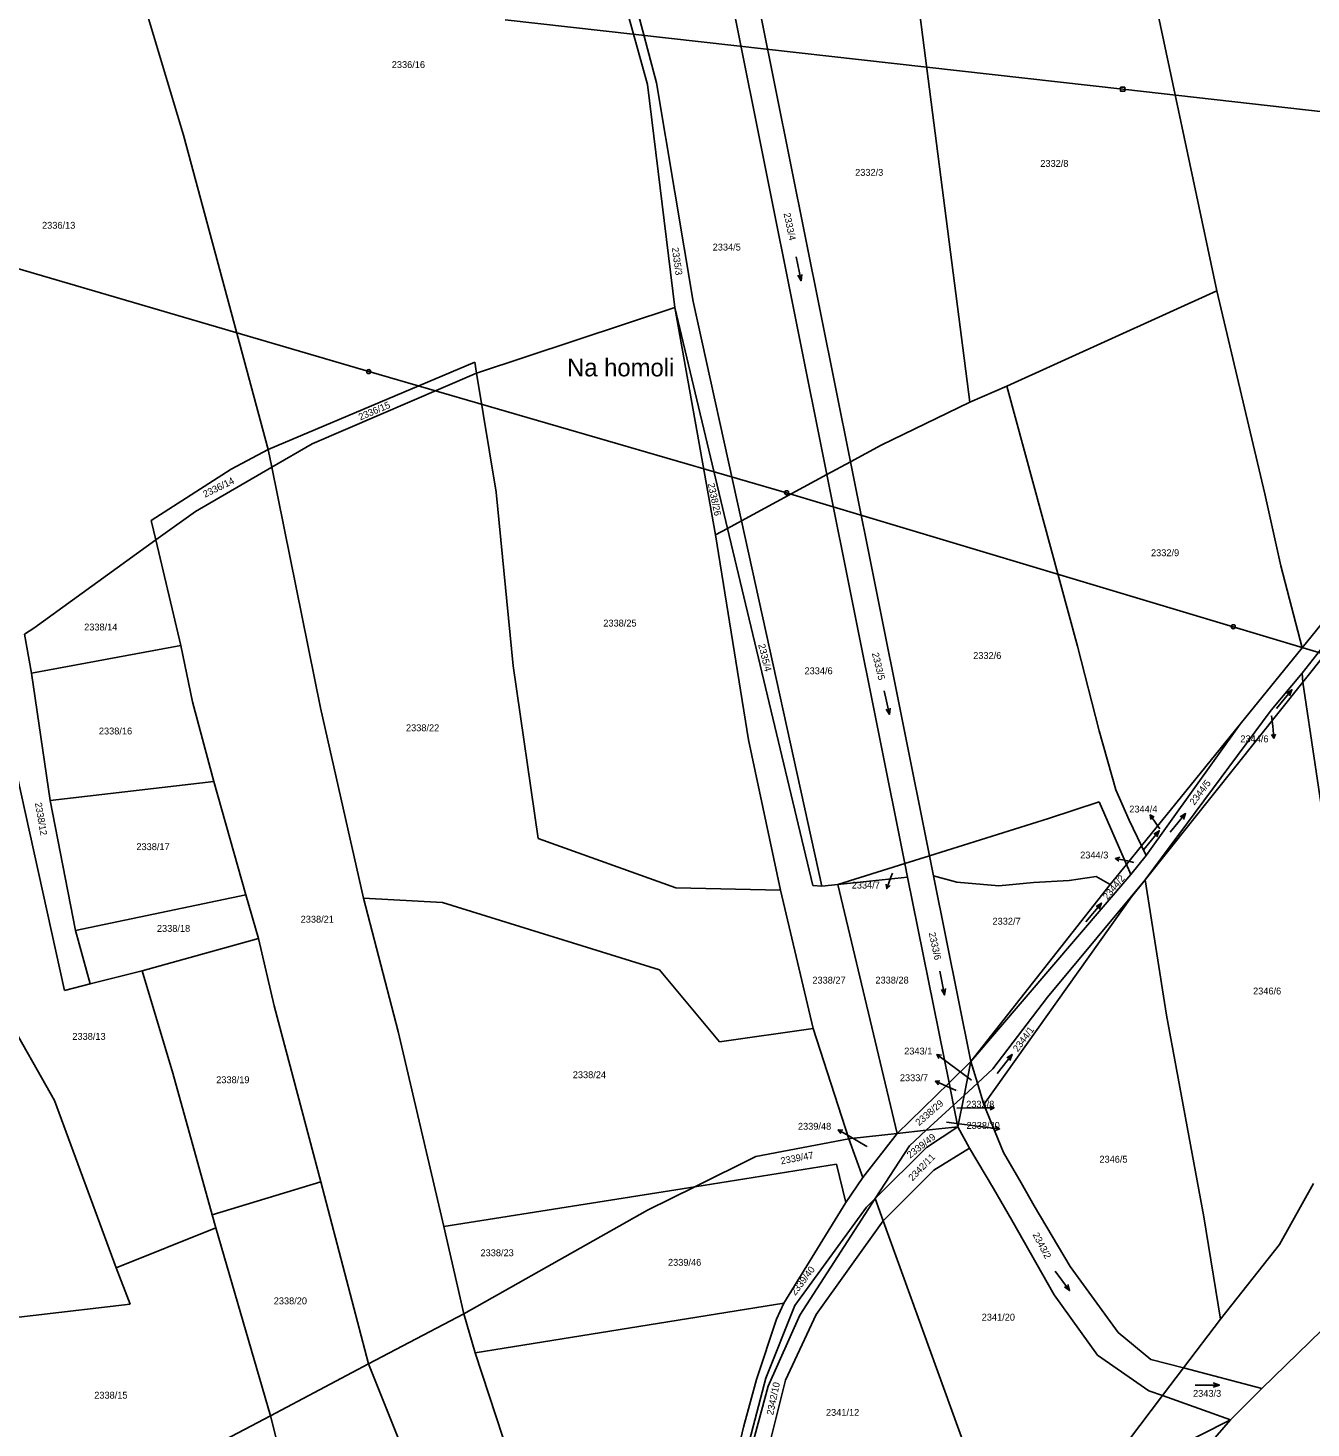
# Model space of a CAD drawing. Extents: x -785744 to -782822, y -1067550 to -1063910.
# Drawn here: x -784569.2 to -784252.2, y -1067114 to -1066768.1 of the extents above; entities that cross this region are included whole.
import ezdxf

# ---------------------------------------------------------------- set-up
doc = ezdxf.new("R2010")
doc.units = 0
for name, color, linetype in [('Hranice obce', 7, 'Continuous'), ('Hranice parcel', 7, 'Continuous'), ('Parcelní čísla', 7, 'Continuous'), ('Pop_ČP_popisy', 7, 'Continuous'), ('Poz_předměty', 7, 'Continuous'), ('Vnitřní kresba', 7, 'Continuous'), ('Značky kultur', 7, 'Continuous')]:
    doc.layers.add(name, color=color, linetype=linetype)

msp = doc.modelspace()

# ---------------------------------------------------------------- linework, layer by layer
at = {"layer": 'Hranice obce'}
msp.add_lwpolyline([(-784228.88, -1067069.75), (-784264.38, -1067104.23), (-784272.17, -1067112.02), (-784297.86, -1067141.59)], dxfattribs=at)
at = {"layer": 'Hranice parcel'}
for points in [[(-784351.64, -1066743.59), (-784336.52, -1066860.57)], [(-784422.15, -1066750.47), (-784413.97, -1066781.67)], [(-784293.05, -1066750.45), (-784275.55, -1066833.03)], [(-784424.77, -1066750.88), (-784416.2, -1066782.12)], [(-784540.2, -1066763.28), (-784530.77, -1066794.6)], [(-784394.66, -1066764.66), (-784371.86, -1066878.44)], [(-784388.23, -1066764.66), (-784366.03, -1066875.28)], [(-784413.97, -1066781.67), (-784404.91, -1066835.67)], [(-784416.2, -1066782.12), (-784409.45, -1066837.16)], [(-784530.77, -1066794.6), (-784509.84, -1066872.27)], [(-784327.4, -1066856.62), (-784275.55, -1066833.03)], [(-784275.55, -1066833.03), (-784263.64, -1066883.19)], [(-784458.38, -1066853.4), (-784409.45, -1066837.16)], [(-784409.45, -1066837.16), (-784396.4, -1066891.77)], [(-784409.45, -1066837.16), (-784399.36, -1066893.37)], [(-784404.91, -1066835.67), (-784392.98, -1066889.91)], [(-784509.84, -1066872.27), (-784458.82, -1066850.73)], [(-784458.82, -1066850.73), (-784458.38, -1066853.4)], [(-784499.03, -1066870.91), (-784458.38, -1066853.4)], [(-784458.38, -1066853.4), (-784453.54, -1066882.78)], [(-784336.52, -1066860.57), (-784327.4, -1066856.62)], [(-784327.4, -1066856.62), (-784309.9, -1066920.9)], [(-784358.44, -1066871.16), (-784336.52, -1066860.57)], [(-784508.95, -1066876.65), (-784499.03, -1066870.91)], [(-784366.03, -1066875.28), (-784358.44, -1066871.16)], [(-784519.04, -1066877.17), (-784509.84, -1066872.27)], [(-784509.84, -1066872.27), (-784508.95, -1066876.65)], [(-784371.86, -1066878.44), (-784366.03, -1066875.28)], [(-784366.03, -1066875.28), (-784346.49, -1066972.63)], [(-784538.77, -1066889.78), (-784519.04, -1066877.17)], [(-784527.79, -1066887.55), (-784508.95, -1066876.65)], [(-784508.95, -1066876.65), (-784496.93, -1066936.07)], [(-784392.98, -1066889.91), (-784371.86, -1066878.44)], [(-784371.86, -1066878.44), (-784352.6, -1066974.54)], [(-784453.54, -1066882.78), (-784449.34, -1066925.72)], [(-784263.64, -1066883.19), (-784259.67, -1066901.04)], [(-784537.62, -1066894.63), (-784527.79, -1066887.55)], [(-784538.77, -1066889.78), (-784537.62, -1066894.63)], [(-784399.36, -1066893.37), (-784396.4, -1066891.77)], [(-784396.4, -1066891.77), (-784392.98, -1066889.91)], [(-784396.4, -1066891.77), (-784375.33, -1066979.96)], [(-784392.98, -1066889.91), (-784373.13, -1066980.16)], [(-784567.79, -1066916.38), (-784537.62, -1066894.63)], [(-784537.62, -1066894.63), (-784531.42, -1066920.66)], [(-784399.36, -1066893.37), (-784391.19, -1066943.98)], [(-784259.67, -1066901.04), (-784254.41, -1066921.28)], [(-784254.29, -1066929.76), (-784231.22, -1066900.81)], [(-784254.42, -1066927.56), (-784238.09, -1066906.74)], [(-784254.41, -1066921.28), (-784242.71, -1066906.87)], [(-784570.05, -1066917.86), (-784567.79, -1066916.38)], [(-784570.05, -1066917.86), (-784568.37, -1066927.54)], [(-784578.46, -1066923.37), (-784560.22, -1067005.94)], [(-784568.37, -1066927.54), (-784531.42, -1066920.66)], [(-784531.42, -1066920.66), (-784528.61, -1066934.61)], [(-784309.9, -1066920.9), (-784304.58, -1066941.77)], [(-784269.74, -1066940.17), (-784254.41, -1066921.28)], [(-784449.34, -1066925.72), (-784443.15, -1066968.35)], [(-784568.37, -1066927.54), (-784563.76, -1066958.96)], [(-784293.21, -1066978.58), (-784254.29, -1066929.76)], [(-784262.12, -1066936.68), (-784254.42, -1066927.56)], [(-784254.42, -1066927.56), (-784254.29, -1066929.76)], [(-784254.29, -1066929.76), (-784239.02, -1067031.89)], [(-784528.61, -1066934.61), (-784523.32, -1066954.27)], [(-784496.93, -1066936.07), (-784486.29, -1066983.11)], [(-784293.21, -1066978.58), (-784262.12, -1066936.68)], [(-784294.14, -1066970.22), (-784269.74, -1066940.17)], [(-784293, -1066972.61), (-784269.74, -1066940.17)], [(-784391.19, -1066943.98), (-784383.31, -1066981.15)], [(-784304.58, -1066941.77), (-784300.43, -1066956.35)], [(-784563.76, -1066958.96), (-784523.32, -1066954.27)], [(-784523.32, -1066954.27), (-784515.42, -1066982.29)], [(-784300.43, -1066956.35), (-784297.19, -1066963.84)], [(-784563.76, -1066958.96), (-784557.51, -1066991.09)], [(-784317.13, -1066963.42), (-784304.54, -1066959.34)], [(-784304.54, -1066959.34), (-784297.83, -1066974.77)], [(-784346.49, -1066972.63), (-784317.13, -1066963.42)], [(-784297.19, -1066963.84), (-784294.14, -1066970.22)], [(-784443.15, -1066968.35), (-784409.16, -1066980.55)], [(-784297.83, -1066974.77), (-784294.14, -1066970.22)], [(-784294.14, -1066970.22), (-784293, -1066972.61)], [(-784369.14, -1066979.73), (-784352.6, -1066974.54)], [(-784352.6, -1066974.54), (-784346.49, -1066972.63)], [(-784352.6, -1066974.54), (-784351.93, -1066977.9)], [(-784346.49, -1066972.63), (-784345.5, -1066977.58)], [(-784301.89, -1066979.77), (-784297.83, -1066974.77)], [(-784297.83, -1066974.77), (-784296.73, -1066977.31)], [(-784296.73, -1066977.31), (-784293, -1066972.61)], [(-784369.14, -1066979.73), (-784351.93, -1066977.9)], [(-784351.93, -1066977.9), (-784341.67, -1067028.72)], [(-784345.5, -1066977.58), (-784336.27, -1067023.45)], [(-784336.27, -1067023.45), (-784296.73, -1066977.31)], [(-784317.35, -1067007.54), (-784293.21, -1066978.58)], [(-784296.59, -1066982.83), (-784293.21, -1066978.58)], [(-784293.21, -1066978.58), (-784287.94, -1067012.03)], [(-784557.51, -1066991.09), (-784515.42, -1066982.29)], [(-784515.42, -1066982.29), (-784512.24, -1066993.05)], [(-784409.16, -1066980.55), (-784383.31, -1066981.15)], [(-784383.31, -1066981.15), (-784375.25, -1067015.34)], [(-784375.33, -1066979.96), (-784373.13, -1066980.16)], [(-784373.13, -1066980.16), (-784369.14, -1066979.73)], [(-784369.14, -1066979.73), (-784354.52, -1067041.24)], [(-784336.27, -1067023.45), (-784301.89, -1066979.77)], [(-784486.29, -1066983.11), (-784466.8, -1066984.16)], [(-784486.29, -1066983.11), (-784477.8, -1067016.09)], [(-784466.8, -1066984.16), (-784413.21, -1067000.81)], [(-784333.05, -1067034.13), (-784296.59, -1066982.83)], [(-784557.51, -1066991.09), (-784553.88, -1067004.31)], [(-784540.97, -1067001.08), (-784512.24, -1066993.05)], [(-784512.24, -1066993.05), (-784508.41, -1067009.75)], [(-784553.88, -1067004.31), (-784540.97, -1067001.08)], [(-784540.97, -1067001.08), (-784533.44, -1067026.37)], [(-784413.21, -1067000.81), (-784398.41, -1067018.62)], [(-784560.22, -1067005.94), (-784553.88, -1067004.31)], [(-784508.41, -1067009.75), (-784496.88, -1067053.21)], [(-784330.82, -1067025.32), (-784317.35, -1067007.54)], [(-784574.73, -1067011.73), (-784562.68, -1067033.12)], [(-784287.94, -1067012.03), (-784278.72, -1067061.82)], [(-784477.8, -1067016.09), (-784466.45, -1067064.22)], [(-784398.41, -1067018.62), (-784375.25, -1067015.34)], [(-784375.25, -1067015.34), (-784366.39, -1067042.59)], [(-784341.67, -1067028.72), (-784336.27, -1067023.45)], [(-784337.94, -1067031.85), (-784336.27, -1067023.45)], [(-784336.27, -1067023.45), (-784334.65, -1067028.83)], [(-784533.44, -1067026.37), (-784523.71, -1067061.34)], [(-784334.65, -1067028.83), (-784330.82, -1067025.32)], [(-784354.52, -1067041.24), (-784341.67, -1067028.72)], [(-784341.67, -1067028.72), (-784340.56, -1067034.25)], [(-784337.94, -1067031.85), (-784334.65, -1067028.83)], [(-784334.65, -1067028.83), (-784333.05, -1067034.13)], [(-784562.68, -1067033.12), (-784547.4, -1067074.41)], [(-784347.31, -1067040.44), (-784340.56, -1067034.25)], [(-784340.56, -1067034.25), (-784337.94, -1067031.85)], [(-784340.56, -1067034.25), (-784339.48, -1067039.58)], [(-784339.48, -1067039.58), (-784337.94, -1067031.85)], [(-784333.05, -1067034.13), (-784328.21, -1067045.93)], [(-784365.83, -1067042.48), (-784354.52, -1067041.24)], [(-784362.96, -1067052.1), (-784354.52, -1067041.24)], [(-784354.52, -1067041.24), (-784347.31, -1067040.44)], [(-784351.43, -1067044.27), (-784347.31, -1067040.44)], [(-784347.31, -1067040.44), (-784339.48, -1067039.58)], [(-784347.21, -1067044.74), (-784339.48, -1067039.58)], [(-784339.48, -1067039.58), (-784336.65, -1067044.91)], [(-784389.42, -1067046.92), (-784366.39, -1067042.59)], [(-784366.39, -1067042.59), (-784365.83, -1067042.48)], [(-784366.39, -1067042.59), (-784362.96, -1067052.1)], [(-784359.95, -1067057.34), (-784351.43, -1067044.27)], [(-784359.95, -1067057.34), (-784347.21, -1067044.74)], [(-784404.49, -1067054.4), (-784389.42, -1067046.92)], [(-784345.43, -1067050.32), (-784336.65, -1067044.91)], [(-784336.65, -1067044.91), (-784330.7, -1067054.89)], [(-784328.21, -1067045.93), (-784323.89, -1067053.46)], [(-784404.49, -1067054.4), (-784369.45, -1067048.84)], [(-784369.45, -1067048.84), (-784367.17, -1067058.3)], [(-784357.96, -1067062.82), (-784345.43, -1067050.32)], [(-784523.71, -1067061.34), (-784496.88, -1067053.21)], [(-784496.88, -1067053.21), (-784485.05, -1067098.2)], [(-784466.45, -1067064.22), (-784404.49, -1067054.4)], [(-784416.13, -1067060.17), (-784404.49, -1067054.4)], [(-784367.17, -1067058.3), (-784362.96, -1067052.1)], [(-784330.7, -1067054.89), (-784326.12, -1067062.64)], [(-784323.89, -1067053.46), (-784320.67, -1067059.16)], [(-784260.04, -1067068.7), (-784251.67, -1067053.63)], [(-784382.48, -1067083.19), (-784367.17, -1067058.3)], [(-784378.55, -1067086.14), (-784359.95, -1067057.34)], [(-784362.06, -1067059.43), (-784359.95, -1067057.34)], [(-784359.95, -1067057.34), (-784357.96, -1067062.82)], [(-784523.71, -1067061.34), (-784522.83, -1067064.58)], [(-784461.51, -1067085.79), (-784416.13, -1067060.17)], [(-784379.78, -1067083.79), (-784362.06, -1067059.43)], [(-784320.67, -1067059.16), (-784311.72, -1067074.15)], [(-784278.72, -1067061.82), (-784274.57, -1067087.16)], [(-784547.4, -1067074.41), (-784522.83, -1067064.58)], [(-784522.83, -1067064.58), (-784509.32, -1067111)], [(-784466.45, -1067064.22), (-784461.51, -1067085.79)], [(-784374.49, -1067085.96), (-784357.96, -1067062.82)], [(-784357.96, -1067062.82), (-784337.85, -1067118.35)], [(-784326.12, -1067062.64), (-784315.67, -1067081.11)], [(-784274.57, -1067087.16), (-784260.04, -1067068.7)], [(-784547.4, -1067074.41), (-784543.96, -1067083.41)], [(-784311.72, -1067074.15), (-784299.91, -1067090.46)], [(-784315.67, -1067081.11), (-784305.02, -1067096)], [(-784592.01, -1067088.99), (-784543.96, -1067083.41)], [(-784485.05, -1067098.2), (-784461.51, -1067085.79)], [(-784461.51, -1067085.79), (-784458.71, -1067095.46)], [(-784458.71, -1067095.46), (-784382.48, -1067083.19)], [(-784386.92, -1067101.67), (-784379.78, -1067083.79)], [(-784386.34, -1067103.66), (-784378.55, -1067086.14)], [(-784384.26, -1067087.15), (-784382.48, -1067083.19)], [(-784382.1, -1067102.21), (-784374.49, -1067085.96)], [(-784389.2, -1067102.07), (-784384.26, -1067087.15)], [(-784283.72, -1067099.19), (-784274.57, -1067087.16)], [(-784299.91, -1067090.46), (-784291.79, -1067097.09)], [(-784458.71, -1067095.46), (-784446.79, -1067131.82)], [(-784305.02, -1067096), (-784292.29, -1067104.83)], [(-784509.32, -1067111), (-784485.05, -1067098.2)], [(-784485.05, -1067098.2), (-784471.41, -1067132.38)], [(-784291.79, -1067097.09), (-784283.72, -1067099.19)], [(-784288.92, -1067106.03), (-784283.72, -1067099.19)], [(-784283.72, -1067099.19), (-784264.38, -1067104.23)], [(-784407.31, -1067179.37), (-784386.92, -1067101.67)], [(-784400.72, -1067176.61), (-784382.1, -1067102.21)], [(-784392.47, -1067113.81), (-784389.2, -1067102.07)], [(-784390.43, -1067118.96), (-784386.34, -1067103.66)], [(-784302.7, -1067124.16), (-784288.92, -1067106.03)], [(-784292.29, -1067104.83), (-784288.92, -1067106.03)], [(-784288.92, -1067106.03), (-784272.17, -1067112.02)], [(-784549.58, -1067132.22), (-784509.32, -1067111)], [(-784509.32, -1067111), (-784507.11, -1067119.85)], [(-784399.83, -1067145.44), (-784392.47, -1067113.81)], [(-784295.41, -1067123.82), (-784272.17, -1067112.02)]]:
    msp.add_lwpolyline(points, dxfattribs=at)
at = {"layer": 'Pop_ČP_popisy'}
for p, q in [((-784261.7, -1066940.63), (-784261.39, -1066943.61)), ((-784290.25, -1066965.05), (-784291.94, -1066962.57)), ((-784297.62, -1066973.93), (-784300.56, -1066973.31)), ((-784356.03, -1066977.93), (-784357.07, -1066980.74)), ((-784342.24, -1067023.52), (-784344.65, -1067021.74)), ((-784342.28, -1067029.55), (-784345.02, -1067028.34)), ((-784333.54, -1067034.92), (-784330.54, -1067034.88)), ((-784366.45, -1067041.85), (-784369.04, -1067040.33)), ((-784332.15, -1067039.75), (-784329.17, -1067040.11))]:
    msp.add_line(p, q, dxfattribs=at)
for points in [[(-784261.97, -1066938.04), (-784261.7, -1066940.63)], [(-784261, -1066942.57), (-784261.39, -1066943.61), (-784261.99, -1066942.67)], [(-784291.79, -1066963.68), (-784291.94, -1066962.57), (-784290.96, -1066963.12)], [(-784289.62, -1066965.97), (-784290.25, -1066965.05)], [(-784299.68, -1066974.01), (-784300.56, -1066973.31), (-784299.47, -1066973.03)], [(-784296, -1066974.27), (-784297.62, -1066973.93)], [(-784355.66, -1066976.92), (-784356.03, -1066977.93)], [(-784356.25, -1066979.98), (-784357.07, -1066980.74), (-784357.19, -1066979.63)], [(-784344.15, -1067022.73), (-784344.65, -1067021.74), (-784343.55, -1067021.93)], [(-784336.1, -1067028.05), (-784342.24, -1067023.52)], [(-784344.31, -1067029.2), (-784345.02, -1067028.34), (-784343.91, -1067028.28)], [(-784339.87, -1067030.62), (-784342.28, -1067029.55)], [(-784331.55, -1067034.39), (-784330.54, -1067034.88), (-784331.53, -1067035.39)], [(-784339.75, -1067035.01), (-784333.54, -1067034.92)], [(-784368.43, -1067041.27), (-784369.04, -1067040.33), (-784367.92, -1067040.41)], [(-784342.32, -1067038.5), (-784332.15, -1067039.75)], [(-784330.1, -1067039.5), (-784329.17, -1067040.11), (-784330.23, -1067040.49)], [(-784361.98, -1067044.48), (-784366.45, -1067041.85)]]:
    msp.add_lwpolyline(points, dxfattribs=at)
at = {"layer": 'Poz_předměty'}
for points in [[(-784451.36, -1066766.13), (-784298.77, -1066783.28)], [(-784298.77, -1066783.28), (-784145.12, -1066800.64)], [(-784587.62, -1066822.95), (-784485.03, -1066853.03)], [(-784485.03, -1066853.03), (-784381.79, -1066882.95)], [(-784381.79, -1066882.95), (-784271.45, -1066916.06)], [(-784271.45, -1066916.06), (-784171.04, -1066946.21)]]:
    msp.add_lwpolyline(points, dxfattribs=at)
msp.add_lwpolyline([(-784299.27, -1066782.78), (-784298.27, -1066782.78), (-784298.27, -1066783.78), (-784299.27, -1066783.78)], close=True, dxfattribs=at)
for centre in [(-784485.03, -1066853.03), (-784381.79, -1066882.95), (-784271.45, -1066916.06)]:
    msp.add_circle(centre, 0.5, dxfattribs=at)
at = {"layer": 'Vnitřní kresba'}
for points in [[(-784345.5, -1066977.58), (-784339.75, -1066979.19)], [(-784320.79, -1066979.26), (-784312.03, -1066978.73)], [(-784312.03, -1066978.73), (-784305.33, -1066977.76)], [(-784305.33, -1066977.76), (-784301.89, -1066979.77)], [(-784339.75, -1066979.19), (-784329.36, -1066980.07)], [(-784329.36, -1066980.07), (-784320.79, -1066979.26)]]:
    msp.add_lwpolyline(points, dxfattribs=at)
at = {"layer": 'Značky kultur'}
for points in [[(-784379.46, -1066824.71), (-784378.24, -1066830.59), (-784378.05, -1066829.02)], [(-784378.24, -1066830.59), (-784379.03, -1066829.22)], [(-784357.68, -1066931.9), (-784356.34, -1066937.74), (-784356.19, -1066936.17)], [(-784260.81, -1066936.22), (-784256.95, -1066931.64), (-784258.3, -1066932.46)], [(-784256.95, -1066931.64), (-784257.53, -1066933.1)], [(-784356.34, -1066937.74), (-784357.16, -1066936.39)], [(-784287.03, -1066966.84), (-784283.21, -1066962.22), (-784284.55, -1066963.05)], [(-784283.21, -1066962.22), (-784283.78, -1066963.69)], [(-784293.58, -1066971.06), (-784289.72, -1066966.46), (-784291.07, -1066967.29)], [(-784289.72, -1066966.46), (-784290.3, -1066967.93)], [(-784307.85, -1066988.95), (-784304.01, -1066984.35), (-784305.35, -1066985.18)], [(-784304.01, -1066984.35), (-784304.59, -1066985.82)], [(-784343.97, -1067001.14), (-784342.75, -1067007.02), (-784342.57, -1067005.45)], [(-784342.75, -1067007.02), (-784343.55, -1067005.65)], [(-784329.77, -1067026.45), (-784326.09, -1067021.71), (-784327.4, -1067022.59)], [(-784326.09, -1067021.71), (-784326.61, -1067023.2)], [(-784315.42, -1067075.24), (-784311.88, -1067080.08), (-784312.36, -1067078.58)], [(-784311.88, -1067080.08), (-784313.17, -1067079.17)], [(-784280.88, -1067103.4), (-784274.88, -1067103.4), (-784276.38, -1067102.9)], [(-784274.88, -1067103.4), (-784276.38, -1067103.9)]]:
    msp.add_lwpolyline(points, dxfattribs=at)

# ---------------------------------------------------------------- texts
at = {"layer": 'Parcelní čísla'}
for s, height, p in [('2336/16', 1.7, (-784479.34, -1066778.03)), ('2332/8', 1.7, (-784319.12, -1066802.44)), ('2332/3', 1.7, (-784364.87, -1066804.65)), ('2336/13', 1.7, (-784565.74, -1066817.73)), ('2334/5', 1.7, (-784400.06, -1066823.11)), ('2332/9', 1.7, (-784291.77, -1066898.63)), ('2338/14', 1.7, (-784555.34, -1066916.98)), ('2338/25', 1.7, (-784427.08, -1066916.01)), ('2332/6', 1.7, (-784335.7, -1066924.02)), ('2334/6', 1.7, (-784377.37, -1066927.8)), ('2338/16', 1.7, (-784551.7, -1066942.67)), ('2338/22', 1.7, (-784475.83, -1066941.88)), ('2344/6', 0.1, (-784261.97, -1066938.04)), ('2344/4', 0.1, (-784289.62, -1066965.97)), ('2338/17', 1.7, (-784542.43, -1066971.25)), ('2344/3', 0.1, (-784296, -1066974.27)), ('2334/7', 0.1, (-784355.66, -1066976.92)), ('2338/21', 1.7, (-784501.85, -1066989.17)), ('2332/7', 1.7, (-784330.93, -1066989.66)), ('2338/18', 1.7, (-784537.36, -1066991.44)), ('2338/27', 1.7, (-784375.43, -1067004.23)), ('2338/28', 1.7, (-784359.86, -1067004.21)), ('2346/6', 1.7, (-784266.56, -1067006.91)), ('2338/13', 1.7, (-784558.25, -1067018.12)), ('2338/19', 1.7, (-784522.72, -1067028.83)), ('2338/24', 1.7, (-784434.62, -1067027.59)), ('2333/7', 0.1, (-784339.87, -1067030.62)), ('2343/1', 0.1, (-784336.1, -1067028.05)), ('2333/8', 0.1, (-784339.75, -1067035.01)), ('2338/30', 0.1, (-784342.32, -1067038.5)), ('2339/48', 0.1, (-784361.98, -1067044.48)), ('2346/5', 1.7, (-784304.52, -1067048.47)), ('2338/23', 1.7, (-784457.42, -1067071.58)), ('2339/46', 1.7, (-784411.1, -1067073.94)), ('2338/20', 1.7, (-784508.5, -1067083.46)), ('2341/20', 1.7, (-784333.6, -1067087.49)), ('2338/15', 1.7, (-784552.84, -1067106.77)), ('2343/3', 1.7, (-784281.39, -1067106.31)), ('2341/12', 1.7, (-784372.07, -1067111.01))]:
    msp.add_text(s, height=height, dxfattribs=at).set_placement(p)
for s, rotation, p in [('2333/4', 281.7545, (-784382.56, -1066813.95)), ('2335/3', 278.1302, (-784410.17, -1066822.44)), ('2336/15', 23.0308, (-784487.11, -1066865.11)), ('2336/14', 26.2515, (-784525.46, -1066884.2)), ('2338/26', 282.0574, (-784401.28, -1066880.76)), ('2335/4', 284.2708, (-784388.83, -1066920.52)), ('2333/5', 283.8036, (-784360.73, -1066922.65)), ('2344/5', 53.1301, (-784281.06, -1066960.27)), ('2338/12', 279.7067, (-784567.5, -1066959.63)), ('2344/2', 50.3691, (-784302.52, -1066983.63)), ('2333/6', 282.4015, (-784346.69, -1066991.74)), ('2344/1', 53.3102, (-784324.68, -1067021.23)), ('2338/29', 41.0447, (-784349.07, -1067039.46)), ('2339/49', 38.0929, (-784351.27, -1067047.49)), ('2339/47', 10.6539, (-784383.12, -1067048.91)), ('2342/11', 45.6848, (-784350.69, -1067053.12)), ('2343/2', 297.8587, (-784321.08, -1067066.25)), ('2342/10', 78.1322, (-784385.12, -1067110.93))]:
    msp.add_text(s, height=1.7, rotation=rotation, dxfattribs=at).set_placement(p)
at = {"layer": 'Pop_ČP_popisy'}
for s, height, p in [('Na homoli', 4.4, (-784436.03, -1066854.21)), ('2344/6', 1.7, (-784269.7, -1066944.61)), ('2344/4', 1.7, (-784297.14, -1066961.95)), ('2344/3', 1.7, (-784309.27, -1066973.31)), ('2334/7', 1.7, (-784365.71, -1066980.74)), ('2343/1', 1.7, (-784352.75, -1067021.74)), ('2333/7', 1.7, (-784353.81, -1067028.34)), ('2333/8', 1.7, (-784337.44, -1067034.88)), ('2339/48', 1.7, (-784379, -1067040.33)), ('2338/30', 1.7, (-784337.35, -1067040.11))]:
    msp.add_text(s, height=height, dxfattribs=at).set_placement(p)
msp.add_text('2339/40', height=1.7, rotation=52.7481, dxfattribs=at).set_placement((-784379.66, -1067081.44))

doc.saveas('drawing.dxf')
